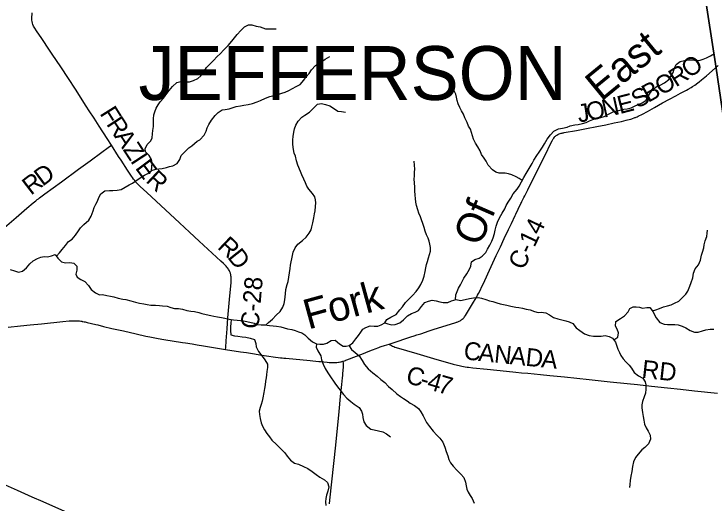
# Model space of a CAD drawing. Extents: x 1442749 to 1756758, y 235267 to 677782.
# Drawn here: x 1576295 to 1587992, y 466342 to 474517 of the extents above; entities that cross this region are included whole.
import ezdxf

# ---------------------------------------------------------------- set-up
doc = ezdxf.new("R2010")
doc.units = 0
for name, color, linetype in [('GM_X_County_Road', 7, 'Continuous'), ('GM_X_County_Road_Text', 7, 'Continuous'), ('GM_X_Minor_River', 7, 'Continuous'), ('GM_X_Minor_River_Text', 7, 'Continuous'), ('GM_X_Township', 7, 'Continuous'), ('GM_X_Township_Road', 7, 'Continuous'), ('GM_X_Township_Road_Text', 7, 'Continuous'), ('GM_X_Township_Text', 7, 'Continuous')]:
    doc.layers.add(name, color=color, linetype=linetype)

msp = doc.modelspace()

# ---------------------------------------------------------------- linework, layer by layer
at = {"layer": 'GM_X_County_Road'}
for points in [[(1577923, 472323), (1577852, 472434), (1577717, 472644), (1577632, 472776), (1577553, 472897), (1577501, 472977), (1577321, 473259), (1577208, 473436), (1577077, 473632), (1576932, 473847), (1576897, 473898), (1576748, 474122), (1576683, 474217), (1576633, 474294), (1576622, 474315), (1576612, 474340), (1576604, 474365), (1576598, 474391), (1576594, 474413), (1576592, 474434), (1576593, 474464), (1576597, 474513), (1576598, 474536)], [(1582565, 468999), (1582612, 469014), (1582925, 469118), (1582980, 469136), (1583027, 469152), (1583091, 469172), (1583231, 469218), (1583297, 469240), (1583677, 469360), (1583690, 469365), (1583696, 469367), (1583710, 469372), (1583721, 469376), (1583734, 469382), (1583749, 469389), (1583760, 469396), (1583774, 469405), (1583785, 469413), (1583798, 469425), (1583807, 469434), (1583815, 469443), (1583825, 469455), (1583841, 469478), (1583890, 469558), (1583973, 469697), (1584027, 469790), (1584042, 469817), (1584057, 469846), (1584077, 469885), (1584118, 469970), (1584139, 470014), (1584214, 470175), (1584353, 470478), (1584422, 470624), (1584488, 470764), (1584557, 470912), (1584606, 471016), (1584669, 471148), (1584679, 471170), (1584719, 471253), (1584764, 471347), (1584774, 471366), (1584783, 471385), (1584816, 471451), (1584830, 471478), (1584880, 471579), (1584928, 471673), (1585003, 471823), (1585133, 472087), (1585185, 472190), (1585249, 472323), (1585286, 472398), (1585293, 472410), (1585304, 472428), (1585310, 472437), (1585314, 472443), (1585328, 472459), (1585335, 472467), (1585345, 472476), (1585355, 472484), (1585368, 472493), (1585380, 472500), (1585393, 472507), (1585406, 472513), (1585422, 472519), (1585437, 472523), (1585453, 472527), (1585465, 472530), (1585475, 472532), (1585488, 472534), (1585692, 472570), (1585864, 472600), (1586037, 472636), (1586185, 472665), (1586326, 472696), (1586445, 472722), (1586524, 472741), (1586544, 472746), (1586602, 472761), (1586617, 472766), (1586629, 472770), (1586659, 472780), (1586672, 472784), (1586680, 472788), (1586690, 472792), (1586709, 472799), (1586726, 472808), (1586798, 472843), (1586879, 472887), (1587000, 472954), (1587134, 473029), (1587250, 473091), (1587353, 473148), (1587431, 473191), (1587534, 473246), (1587563, 473262), (1587610, 473289), (1587631, 473302), (1587670, 473328), (1587720, 473364), (1587745, 473383), (1587782, 473414), (1587865, 473485), (1588063, 473656)], [(1579831, 468911), (1579833, 468941), (1579841, 469055), (1579856, 469255), (1579870, 469438), (1579903, 469807), (1579918, 469967), (1579923, 470026), (1579925, 470062), (1579925, 470081), (1579925, 470101), (1579923, 470124), (1579920, 470141), (1579918, 470159), (1579911, 470184), (1579902, 470208), (1579894, 470223), (1579886, 470239), (1579878, 470253), (1579865, 470272), (1579852, 470287), (1579839, 470300), (1579828, 470312), (1579810, 470329), (1579795, 470344), (1579749, 470386), (1579387, 470720), (1579228, 470867), (1579060, 471023), (1578903, 471168), (1578512, 471532), (1578404, 471632), (1578357, 471679), (1578342, 471696), (1578322, 471718), (1578306, 471739), (1578292, 471758), (1578275, 471782), (1578258, 471806), (1578193, 471905), (1578084, 472072), (1578043, 472136), (1577923, 472323)], [(1576199, 469281), (1576405, 469302), (1576565, 469318), (1576754, 469338), (1577110, 469376), (1577218, 469386), (1577241, 469387), (1577283, 469389), (1577300, 469390), (1577315, 469390), (1577330, 469390), (1577341, 469389), (1577350, 469389), (1577371, 469388), (1577387, 469386), (1577413, 469382), (1577427, 469380), (1577436, 469378), (1577446, 469377), (1577465, 469373), (1577483, 469369), (1577498, 469366), (1577520, 469361), (1577662, 469326), (1577693, 469318), (1577792, 469294), (1577930, 469262), (1578122, 469218), (1578336, 469169), (1578499, 469132), (1578563, 469119), (1578705, 469091), (1578799, 469075), (1579112, 469026), (1579163, 469018), (1579272, 469001), (1579353, 468988), (1579463, 468970), (1579664, 468938), (1579831, 468911)], [(1581793, 468713), (1581800, 468715), (1581819, 468721), (1581833, 468726), (1581842, 468730), (1581856, 468735), (1582134, 468844), (1582176, 468860), (1582242, 468885), (1582286, 468902), (1582345, 468926), (1582375, 468936), (1582394, 468944), (1582416, 468951), (1582433, 468957), (1582485, 468974), (1582565, 468999)], [(1582565, 468999), (1582583, 468986), (1582602, 468976), (1582620, 468966), (1582640, 468957), (1582660, 468949), (1582680, 468942), (1583027, 468843), (1583307, 468760), (1583635, 468664), (1583658, 468657), (1583684, 468651), (1583708, 468645), (1583732, 468639), (1583756, 468634), (1583781, 468629), (1583804, 468624), (1583836, 468619), (1583866, 468615), (1583892, 468612), (1583964, 468602), (1584202, 468578), (1584522, 468545), (1584682, 468529), (1584777, 468521), (1584881, 468510), (1585093, 468489), (1585250, 468473), (1585492, 468450), (1585906, 468408), (1586258, 468369), (1586539, 468341), (1586712, 468322), (1586950, 468297), (1587217, 468268), (1587433, 468246), (1587668, 468219), (1588052, 468178)], [(1579831, 468911), (1580082, 468871), (1580182, 468856), (1580282, 468839), (1580435, 468815), (1580552, 468797), (1580623, 468787), (1580747, 468771), (1580777, 468768), (1580805, 468765), (1580835, 468762), (1581244, 468722), (1581291, 468718), (1581386, 468709), (1581418, 468706), (1581527, 468695), (1581560, 468692), (1581583, 468690), (1581593, 468690), (1581601, 468690), (1581609, 468689), (1581618, 468689), (1581629, 468689), (1581645, 468689), (1581659, 468690), (1581672, 468690), (1581678, 468691), (1581690, 468691), (1581715, 468695), (1581730, 468697), (1581751, 468702), (1581762, 468704), (1581773, 468707), (1581789, 468711), (1581793, 468713)], [(1576146, 466646), (1576350, 466556), (1576590, 466448), (1576776, 466367), (1577190, 466182), (1577372, 466101), (1577491, 466047)]]:
    msp.add_lwpolyline(points, dxfattribs=at)
at = {"layer": 'GM_X_Minor_River'}
for points in [[(1579369, 473439), (1579416, 473483), (1579467, 473552), (1579514, 473622), (1579561, 473673), (1579628, 473739), (1579689, 473808), (1579742, 473853), (1579803, 473915), (1579872, 473990), (1579937, 474065), (1579982, 474117), (1580023, 474175), (1580086, 474242), (1580147, 474303), (1580215, 474338), (1580271, 474336), (1580339, 474315), (1580409, 474302), (1580497, 474271), (1580561, 474266), (1580626, 474267), (1580676, 474268)], [(1579353, 472391), (1579399, 472415), (1579471, 472490), (1579504, 472556), (1579524, 472614), (1579551, 472669), (1579596, 472741), (1579657, 472818), (1579704, 472872), (1579771, 472915), (1579823, 472922), (1579888, 472934), (1579940, 472947), (1580006, 472968), (1580077, 472983), (1580135, 472992), (1580210, 473006), (1580280, 473019), (1580358, 473048), (1580413, 473069), (1580498, 473112), (1580568, 473139), (1580635, 473152), (1580691, 473168), (1580770, 473191), (1580826, 473210), (1580890, 473237), (1580951, 473271), (1581008, 473304), (1581076, 473339), (1581140, 473412), (1581178, 473464), (1581225, 473524), (1581266, 473585), (1581333, 473656), (1581420, 473711), (1581497, 473761), (1581570, 473804)], [(1583673, 469741), (1583678, 469822), (1583701, 469880), (1583722, 469933), (1583757, 469991), (1583782, 470045), (1583814, 470099), (1583860, 470174), (1583907, 470250), (1583931, 470303), (1583942, 470373), (1583997, 470411), (1584068, 470434), (1584118, 470467), (1584177, 470531), (1584208, 470583), (1584245, 470650), (1584278, 470722), (1584301, 470774), (1584326, 470850), (1584337, 470902), (1584352, 470972), (1584375, 471039), (1584410, 471111), (1584455, 471189), (1584496, 471262), (1584521, 471318), (1584551, 471370), (1584596, 471437), (1584638, 471511), (1584701, 471586), (1584736, 471640), (1584775, 471710), (1584814, 471785), (1584855, 471849), (1584886, 471905), (1584920, 471964), (1584951, 472020), (1584984, 472076), (1585033, 472151), (1585070, 472209), (1585127, 472290), (1585160, 472348), (1585207, 472424), (1585260, 472495), (1585318, 472559), (1585392, 472598), (1585461, 472609), (1585539, 472626), (1585589, 472645), (1585664, 472662), (1585722, 472670), (1585797, 472685), (1585855, 472704), (1585913, 472729), (1585966, 472753), (1586030, 472774), (1586101, 472789), (1586157, 472806), (1586230, 472841), (1586307, 472882), (1586367, 472900), (1586417, 472909), (1586488, 472926), (1586542, 472934), (1586608, 472949), (1586677, 472982), (1586741, 473009), (1586794, 473031), (1586855, 473070), (1586900, 473147), (1586929, 473205), (1586971, 473257), (1587040, 473310), (1587093, 473325), (1587163, 473365), (1587236, 473424), (1587287, 473499), (1587314, 473551), (1587325, 473603), (1587360, 473673), (1587427, 473724), (1587497, 473739), (1587576, 473750), (1587626, 473753), (1587702, 473742), (1587762, 473744), (1587812, 473759), (1587865, 473782), (1587932, 473818), (1588002, 473855)], [(1578594, 471899), (1578599, 471961), (1578602, 472031), (1578591, 472085), (1578553, 472152), (1578492, 472215), (1578487, 472265), (1578520, 472333), (1578579, 472396), (1578602, 472448), (1578611, 472514), (1578616, 472568), (1578623, 472638), (1578624, 472700), (1578626, 472764), (1578631, 472832), (1578650, 472884), (1578671, 472944), (1578702, 472996), (1578739, 473049), (1578792, 473109), (1578849, 473186), (1578888, 473238), (1578945, 473307), (1579016, 473374), (1579082, 473388), (1579156, 473384), (1579230, 473385), (1579296, 473407), (1579369, 473439)], [(1584788, 471736), (1584739, 471768), (1584686, 471795), (1584612, 471828), (1584560, 471845), (1584500, 471856), (1584450, 471858), (1584400, 471855), (1584348, 471870), (1584288, 471912), (1584221, 471987), (1584184, 472054), (1584154, 472105), (1584109, 472169), (1584086, 472228), (1584045, 472298), (1584009, 472355), (1583972, 472426), (1583959, 472482), (1583941, 472538), (1583922, 472591), (1583889, 472643), (1583865, 472704), (1583830, 472782), (1583807, 472843), (1583772, 472899), (1583743, 472956), (1583719, 473016), (1583698, 473069), (1583689, 473125), (1583677, 473175), (1583646, 473246)], [(1580499, 469317), (1580549, 469359), (1580612, 469414), (1580673, 469480), (1580745, 469545), (1580788, 469615), (1580808, 469678), (1580821, 469736), (1580828, 469788), (1580831, 469839), (1580836, 469913), (1580857, 469995), (1580876, 470046), (1580887, 470116), (1580898, 470190), (1580909, 470262), (1580917, 470316), (1580928, 470372), (1580935, 470422), (1580946, 470480), (1580958, 470534), (1580991, 470606), (1581040, 470670), (1581113, 470729), (1581176, 470788), (1581227, 470852), (1581258, 470907), (1581271, 470961), (1581286, 471025), (1581303, 471111), (1581318, 471177), (1581325, 471227), (1581332, 471299), (1581337, 471359), (1581335, 471409), (1581322, 471462), (1581285, 471518), (1581223, 471589), (1581190, 471640), (1581165, 471696), (1581139, 471757), (1581102, 471829), (1581081, 471886), (1581038, 471991), (1581013, 472061), (1580996, 472139), (1580979, 472190), (1580966, 472254), (1580955, 472336), (1580954, 472413), (1580960, 472471), (1580969, 472541), (1580982, 472599), (1581003, 472659), (1581042, 472728), (1581105, 472791), (1581156, 472827), (1581231, 472876), (1581304, 472947), (1581369, 473007), (1581433, 473022), (1581499, 473005), (1581571, 472984), (1581633, 472941), (1581706, 472894), (1581770, 472887), (1581834, 472876)], [(1577005, 470466), (1577054, 470526), (1577097, 470578), (1577156, 470647), (1577207, 470711), (1577264, 470750), (1577323, 470822), (1577370, 470891), (1577405, 470943), (1577462, 471000), (1577547, 471073), (1577584, 471137), (1577617, 471226), (1577634, 471284), (1577661, 471338), (1577690, 471390), (1577710, 471452), (1577745, 471509), (1577810, 471559), (1577888, 471568), (1577946, 471565), (1578021, 471570), (1578083, 471583), (1578155, 471624), (1578220, 471659), (1578274, 471689), (1578333, 471726), (1578404, 471777), (1578477, 471820), (1578529, 471851), (1578594, 471899), (1578664, 471924), (1578714, 471929), (1578769, 471934), (1578841, 471953), (1578893, 471965), (1578951, 471976), (1579022, 472017), (1579067, 472085), (1579088, 472153), (1579155, 472216), (1579214, 472279), (1579265, 472311), (1579353, 472391)], [(1582493, 469353), (1582526, 469410), (1582594, 469449), (1582679, 469496), (1582744, 469569), (1582785, 469623), (1582838, 469694), (1582895, 469748), (1582952, 469809), (1583013, 469878), (1583058, 469938), (1583091, 469994), (1583128, 470065), (1583151, 470135), (1583164, 470215), (1583177, 470271), (1583190, 470327), (1583204, 470381), (1583223, 470441), (1583240, 470499), (1583255, 470553), (1583256, 470615), (1583246, 470667), (1583233, 470717), (1583216, 470772), (1583188, 470826), (1583167, 470889), (1583148, 470947), (1583129, 471015), (1583104, 471076), (1583088, 471128), (1583061, 471187), (1583042, 471241), (1583019, 471314), (1583007, 471372), (1583002, 471432), (1582997, 471490), (1582994, 471558), (1582993, 471619), (1582986, 471699), (1582982, 471751), (1582985, 471817), (1582990, 471871), (1582993, 471925), (1582989, 471987), (1582982, 472056)], [(1586962, 469555), (1587018, 469572), (1587083, 469593), (1587147, 469620), (1587213, 469636), (1587274, 469657), (1587332, 469684), (1587403, 469719), (1587468, 469777), (1587519, 469832), (1587554, 469884), (1587587, 469968), (1587612, 470031), (1587637, 470109), (1587652, 470183), (1587677, 470255), (1587734, 470324), (1587765, 470404), (1587784, 470484), (1587799, 470538), (1587822, 470608), (1587827, 470658), (1587844, 470726), (1587875, 470796), (1587880, 470852), (1587882, 470904)], [(1576233, 470245), (1576305, 470222), (1576369, 470201), (1576439, 470216), (1576506, 470271), (1576561, 470341), (1576616, 470390), (1576687, 470431), (1576745, 470453), (1576801, 470462), (1576855, 470459), (1576919, 470472), (1576984, 470497), (1577027, 470433), (1577090, 470372), (1577156, 470357), (1577228, 470360), (1577292, 470351), (1577345, 470300), (1577346, 470234), (1577327, 470170), (1577351, 470120), (1577414, 470077), (1577476, 470044), (1577537, 469981), (1577586, 469912), (1577655, 469857), (1577721, 469824), (1577775, 469827), (1577845, 469812), (1577907, 469801), (1577963, 469790), (1578034, 469767), (1578112, 469750), (1578166, 469742), (1578246, 469722), (1578326, 469701), (1578392, 469684), (1578465, 469669), (1578521, 469663), (1578583, 469652), (1578659, 469651), (1578725, 469646), (1578777, 469641), (1578855, 469632), (1578913, 469611), (1578977, 469594), (1579043, 469591), (1579113, 469580), (1579183, 469561), (1579250, 469548), (1579309, 469542)], [(1579309, 469542), (1579383, 469527), (1579434, 469512), (1579506, 469491), (1579582, 469476), (1579636, 469465), (1579698, 469452), (1579762, 469443), (1579816, 469433), (1579892, 469414), (1579964, 469405), (1580023, 469396), (1580081, 469391), (1580157, 469380), (1580237, 469367), (1580307, 469346), (1580361, 469327), (1580427, 469319), (1580487, 469318), (1580563, 469311), (1580625, 469304), (1580679, 469299), (1580751, 469286), (1580809, 469268), (1580867, 469253), (1580937, 469240), (1580993, 469225), (1581051, 469204), (1581103, 469188), (1581156, 469155), (1581212, 469100), (1581281, 469039), (1581349, 469004), (1581405, 468997), (1581469, 468998), (1581522, 469016), (1581596, 469061), (1581663, 469066), (1581734, 469003), (1581794, 468964), (1581846, 468963), (1581898, 468973), (1581955, 469018), (1582006, 469084), (1582053, 469141), (1582088, 469197), (1582122, 469249), (1582173, 469278), (1582249, 469305), (1582316, 469300), (1582372, 469301), (1582428, 469321), (1582489, 469354), (1582541, 469337), (1582609, 469322), (1582663, 469326), (1582741, 469355), (1582806, 469402), (1582871, 469471), (1582938, 469511), (1583001, 469532), (1583055, 469561), (1583106, 469625), (1583161, 469692), (1583222, 469719), (1583280, 469733), (1583350, 469720), (1583408, 469703), (1583468, 469692), (1583542, 469695), (1583607, 469722), (1583681, 469743), (1583755, 469730), (1583834, 469742), (1583904, 469761), (1583976, 469770), (1584049, 469775), (1584109, 469768), (1584179, 469743), (1584241, 469724), (1584297, 469711), (1584364, 469687), (1584420, 469674), (1584476, 469659), (1584528, 469650), (1584598, 469633), (1584678, 469614), (1584732, 469608), (1584792, 469599), (1584854, 469584), (1584920, 469569), (1584994, 469544), (1585052, 469529), (1585106, 469535), (1585184, 469520), (1585242, 469487), (1585312, 469446), (1585380, 469419), (1585448, 469406), (1585517, 469387), (1585573, 469370)], [(1586320, 469068), (1586384, 469115), (1586395, 469189), (1586372, 469246), (1586347, 469296), (1586352, 469374), (1586429, 469429), (1586495, 469473), (1586556, 469540), (1586585, 469596), (1586640, 469623), (1586694, 469624), (1586748, 469616), (1586800, 469597), (1586868, 469612), (1586920, 469609), (1586974, 469540), (1586999, 469486), (1587024, 469436), (1587089, 469359), (1587157, 469334), (1587213, 469327), (1587271, 469324), (1587338, 469329), (1587394, 469323), (1587458, 469300), (1587519, 469269), (1587595, 469226), (1587669, 469199), (1587727, 469200), (1587800, 469221), (1587858, 469236), (1587926, 469246), (1587992, 469249)], [(1579925, 469410), (1579918, 469343), (1579913, 469293), (1579910, 469225), (1579917, 469155), (1579981, 469136), (1580033, 469133), (1580105, 469120), (1580167, 469114), (1580241, 469098), (1580311, 469076), (1580336, 469007), (1580341, 468953), (1580381, 468876), (1580442, 468799), (1580489, 468734), (1580532, 468666), (1580533, 468610), (1580522, 468540), (1580514, 468486), (1580507, 468434), (1580500, 468380), (1580491, 468320), (1580478, 468254), (1580470, 468188), (1580452, 468100), (1580444, 468044), (1580427, 467990), (1580410, 467938), (1580393, 467878), (1580396, 467820), (1580408, 467757), (1580427, 467685), (1580446, 467629), (1580479, 467564), (1580517, 467507), (1580562, 467449), (1580605, 467392), (1580680, 467319), (1580819, 467181), (1580860, 467128), (1580916, 467057), (1580981, 467010), (1581051, 466989), (1581135, 466952), (1581207, 466921), (1581280, 466870), (1581342, 466821), (1581407, 466774), (1581481, 466731), (1581534, 466686), (1581555, 466614), (1581538, 466542), (1581519, 466474), (1581507, 466420), (1581502, 466364), (1581505, 466302)], [(1585573, 469370), (1585633, 469343), (1585690, 469270), (1585750, 469226), (1585827, 469170), (1585907, 469141), (1585981, 469130), (1586051, 469129), (1586104, 469131), (1586174, 469142), (1586238, 469127), (1586298, 469098), (1586345, 469033), (1586370, 468963), (1586387, 468913), (1586411, 468856), (1586436, 468806), (1586476, 468755), (1586519, 468702), (1586574, 468648), (1586614, 468597), (1586659, 468524), (1586728, 468467), (1586802, 468430), (1586841, 468370), (1586851, 468319), (1586852, 468243), (1586845, 468177), (1586826, 468117), (1586795, 468041), (1586788, 467985), (1586787, 467935), (1586798, 467855), (1586806, 467787), (1586819, 467726), (1586832, 467662), (1586861, 467598), (1586893, 467545), (1586924, 467477), (1586931, 467410), (1586898, 467333), (1586835, 467269), (1586784, 467230), (1586727, 467158), (1586682, 467105), (1586645, 467029), (1586630, 466951), (1586619, 466869), (1586600, 466789), (1586591, 466719), (1586586, 466653), (1586581, 466603)], [(1581347, 469005), (1581344, 468950), (1581371, 468885), (1581420, 468801), (1581434, 468738), (1581461, 468666), (1581492, 468593), (1581539, 468518), (1581596, 468432), (1581631, 468381), (1581669, 468328), (1581722, 468258), (1581763, 468207), (1581801, 468154), (1581856, 468095), (1581924, 468038), (1581979, 467996), (1582061, 467938), (1582100, 467880), (1582119, 467825), (1582124, 467769), (1582142, 467701), (1582181, 467636), (1582260, 467577), (1582316, 467564), (1582386, 467551), (1582456, 467534), (1582520, 467496), (1582587, 467447)], [(1581894, 468972), (1581935, 468910), (1581995, 468859), (1582064, 468804), (1582113, 468725), (1582152, 468657), (1582214, 468588), (1582293, 468517), (1582364, 468460), (1582424, 468407), (1582491, 468356), (1582553, 468291), (1582616, 468242), (1582693, 468165), (1582751, 468124), (1582805, 468089), (1582862, 468048), (1582916, 468014), (1582988, 467971), (1583055, 467922), (1583094, 467865), (1583134, 467798), (1583161, 467742), (1583190, 467687), (1583237, 467619), (1583301, 467542), (1583362, 467477), (1583409, 467426), (1583459, 467359), (1583496, 467274), (1583515, 467204), (1583544, 467129), (1583561, 467071), (1583588, 467013), (1583636, 466956), (1583697, 466889), (1583764, 466826), (1583810, 466769), (1583839, 466689), (1583850, 466632), (1583863, 466572), (1583885, 466522), (1583920, 466469), (1583953, 466415), (1583982, 466340)]]:
    msp.add_lwpolyline(points, dxfattribs=at)
at = {"layer": 'GM_X_Township'}
for points in [[(1590479, 454965), (1590579, 456501), (1589955, 460536), (1589883, 461020), (1588851, 468025), (1588027, 473613), (1587351, 478007), (1587012, 480278), (1582429, 481309), (1581429, 481533), (1582700, 483060), (1583514, 484036), (1583852, 484442), (1586641, 487791), (1589558, 491294), (1589677, 491347), (1594192, 493386), (1600346, 496373)], [(1571453, 483622), (1577047, 482527), (1577422, 482442), (1581429, 481533), (1582429, 481309), (1587012, 480278), (1587351, 478007), (1588027, 473613), (1588851, 468025), (1589883, 461020)]]:
    msp.add_lwpolyline(points, dxfattribs=at)
at = {"layer": 'GM_X_Township_Road'}
for points in [[(1576050, 470880), (1576331, 471117), (1576507, 471269), (1576615, 471360), (1576658, 471395), (1576684, 471415), (1576702, 471429), (1576723, 471444), (1576810, 471509), (1577088, 471713), (1577374, 471923), (1577567, 472063), (1577760, 472205), (1577869, 472284), (1577923, 472323)], [(1581567, 466327), (1581574, 466390), (1581671, 467309), (1581728, 467871), (1581753, 468123), (1581775, 468326), (1581785, 468436), (1581789, 468476), (1581791, 468499), (1581800, 468621), (1581801, 468629), (1581801, 468638), (1581801, 468645), (1581801, 468655), (1581801, 468670), (1581800, 468674), (1581800, 468678), (1581800, 468680), (1581800, 468682), (1581799, 468685), (1581799, 468688), (1581798, 468694), (1581797, 468699), (1581795, 468705), (1581795, 468708), (1581793, 468713)]]:
    msp.add_lwpolyline(points, dxfattribs=at)

# ---------------------------------------------------------------- texts
at = {"layer": 'GM_X_County_Road_Text'}
for s, rotation, p in [('O', 36.8098, (1587585, 473433)), ('R', 32.4013, (1587356, 473287)), ('O', 29.0392, (1587109, 473149)), ('B', 28.7544, (1586891, 473029)), ('E', 14.4731, (1586419, 472843)), ('S', 29.3568, (1586715, 472930)), ('O', 12.1088, (1585890, 472727)), ('N', 12.5324, (1586151, 472783)), ('F', 302.1303, (1577719, 472854)), ('J', 8.3764, (1585730, 472703)), ('R', 303.0309, (1577829, 472678)), ('A', 303.0359, (1577964, 472471)), ('Z', 303.0398, (1578107, 472250)), ('I', 303.1207, (1578230, 472061)), ('E', 306.7869, (1578309, 471941)), ('R', 316.9961, (1578483, 471718)), ('C-14', 64.6492, (1584810, 470222)), ('R', 316.4849, (1579680, 470609)), ('D', 308.4044, (1579851, 470447)), ('C-28', 85.2689, (1580381, 469246)), ('C', 353.4758, (1583798, 468747)), ('A', 354.1913, (1584046, 468718)), ('N', 354.1908, (1584309, 468692)), ('A', 354.1872, (1584572, 468665)), ('D', 354.1856, (1584834, 468638)), ('A', 354.1893, (1585097, 468612)), ('RD', 353.5956, (1586774, 468438)), ('C', 343.571, (1582825, 468358)), ('4', 343.6633, (1583180, 468253)), ('-', 343.5883, (1583061, 468288)), ('7', 344.028, (1583359, 468201))]:
    msp.add_text(s, height=300, rotation=rotation, dxfattribs=at).set_placement(p)
at = {"layer": 'GM_X_Minor_River_Text'}
for s, rotation, p in [('East', 39.3439, (1586106, 473043)), ('Of', 66.3746, (1584075, 470611)), ('Fork', 15.375, (1581211, 469240))]:
    msp.add_text(s, height=500, rotation=rotation, dxfattribs=at).set_placement(p)
at = {"layer": 'GM_X_Township_Road_Text'}
for s, rotation, p in [('D', 36.5424, (1576772, 471627)), ('R', 37.4717, (1576577, 471478))]:
    msp.add_text(s, height=300, rotation=rotation, dxfattribs=at).set_placement(p)
at = {"layer": 'GM_X_Township_Text'}
msp.add_text('JEFFERSON', height=900, rotation=0, dxfattribs=at).set_placement((1578376, 473080))

doc.saveas('drawing.dxf')
